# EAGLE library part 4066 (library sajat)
Quad bilateral ANALOG SWITCH
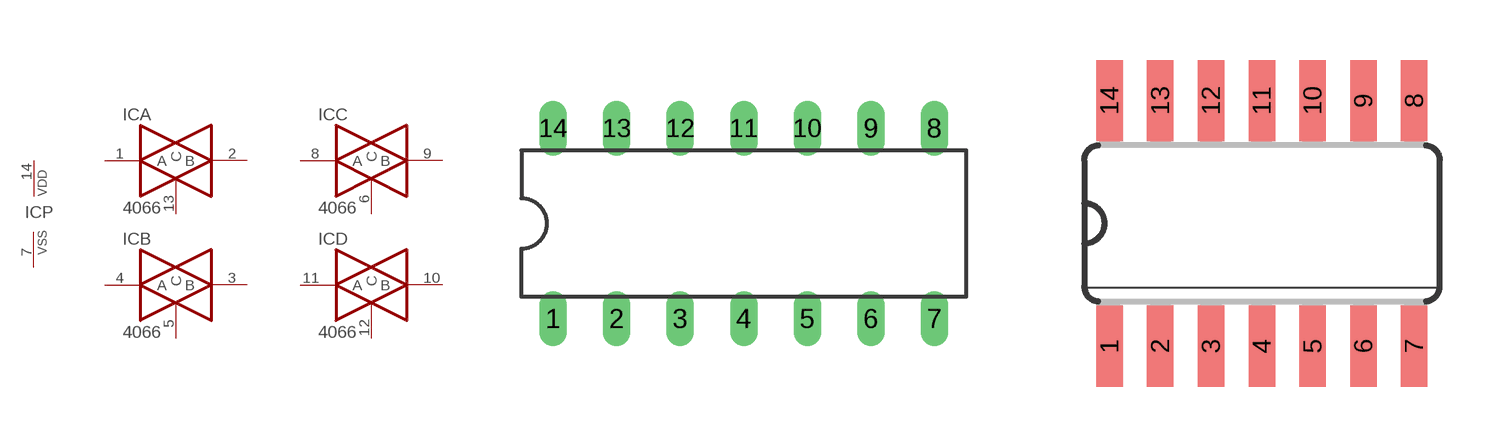
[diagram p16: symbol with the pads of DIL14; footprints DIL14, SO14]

Designator prefix IC; gates A=4066 B=4066 C=4066 D=4066 P=PWRN

## 4066N  [DIL14]
1  A:A  hiz
2  A:B  hiz
3  B:B  hiz
4  B:A  hiz
5  B:C  in
6  C:C  in
7  P:VSS  pwr
8  C:A  hiz
9  C:B  hiz
10  D:B  hiz
11  D:A  hiz
12  D:C  in
13  A:C  in
14  P:VDD  pwr

## 4066D  [SO14]
Pads as for DIL14

## Footprint DIL14 (pad centres in mm)
Dual In Line Package
drill 0.6 pad 1.016 long: 1 -7.62,-3.81; 2 -5.08,-3.81; 3 -2.54,-3.81; 4 0,-3.81; 5 2.54,-3.81; 6 5.08,-3.81; 7 7.62,-3.81; 8 7.62,3.81; 9 5.08,3.81; 10 2.54,3.81; 11 0,3.81; 12 -2.54,3.81; 13 -5.08,3.81; 14 -7.62,3.81

## Footprint SO14 (pad centres in mm)
Small Outline package 150 mil
smd 0.66 x 2.032: 1 -3.81,-3.073; 2 -2.54,-3.073; 3 -1.27,-3.073; 4 0,-3.073; 5 1.27,-3.073; 6 2.54,-3.073; 7 3.81,-3.073; 8 3.81,3.073; 9 2.54,3.073; 10 1.27,3.073; 11 0,3.073; 12 -1.27,3.073; 13 -2.54,3.073; 14 -3.81,3.073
